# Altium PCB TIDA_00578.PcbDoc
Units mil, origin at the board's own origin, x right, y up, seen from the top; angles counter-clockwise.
Board outline 1181.1 x 1181.1 mil, 2 copper layers (Top Layer, Bottom Layer); 21 components, 9 nets, 32 pads, 7 vias.
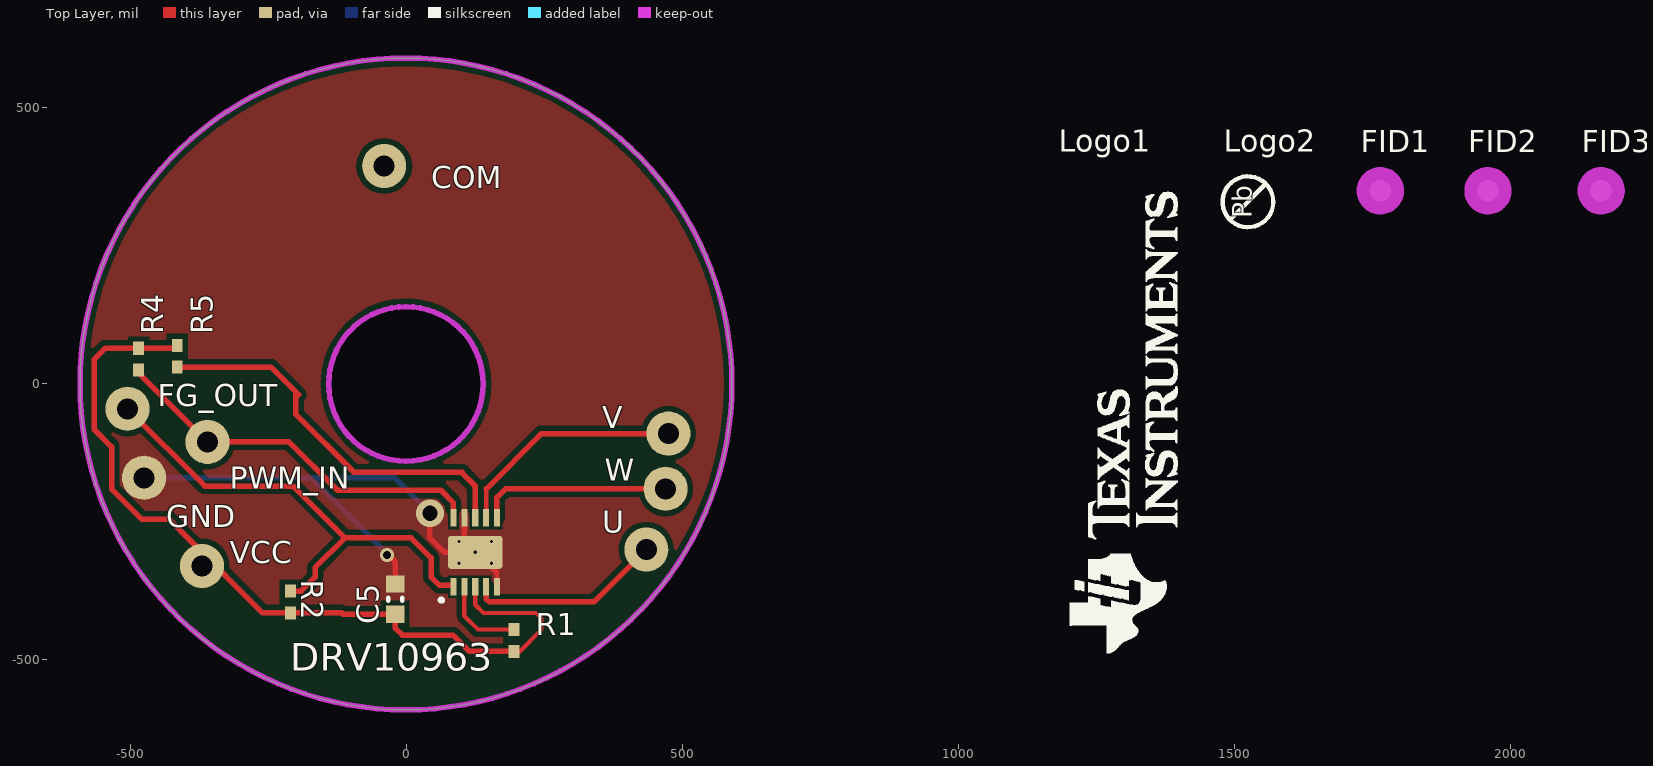
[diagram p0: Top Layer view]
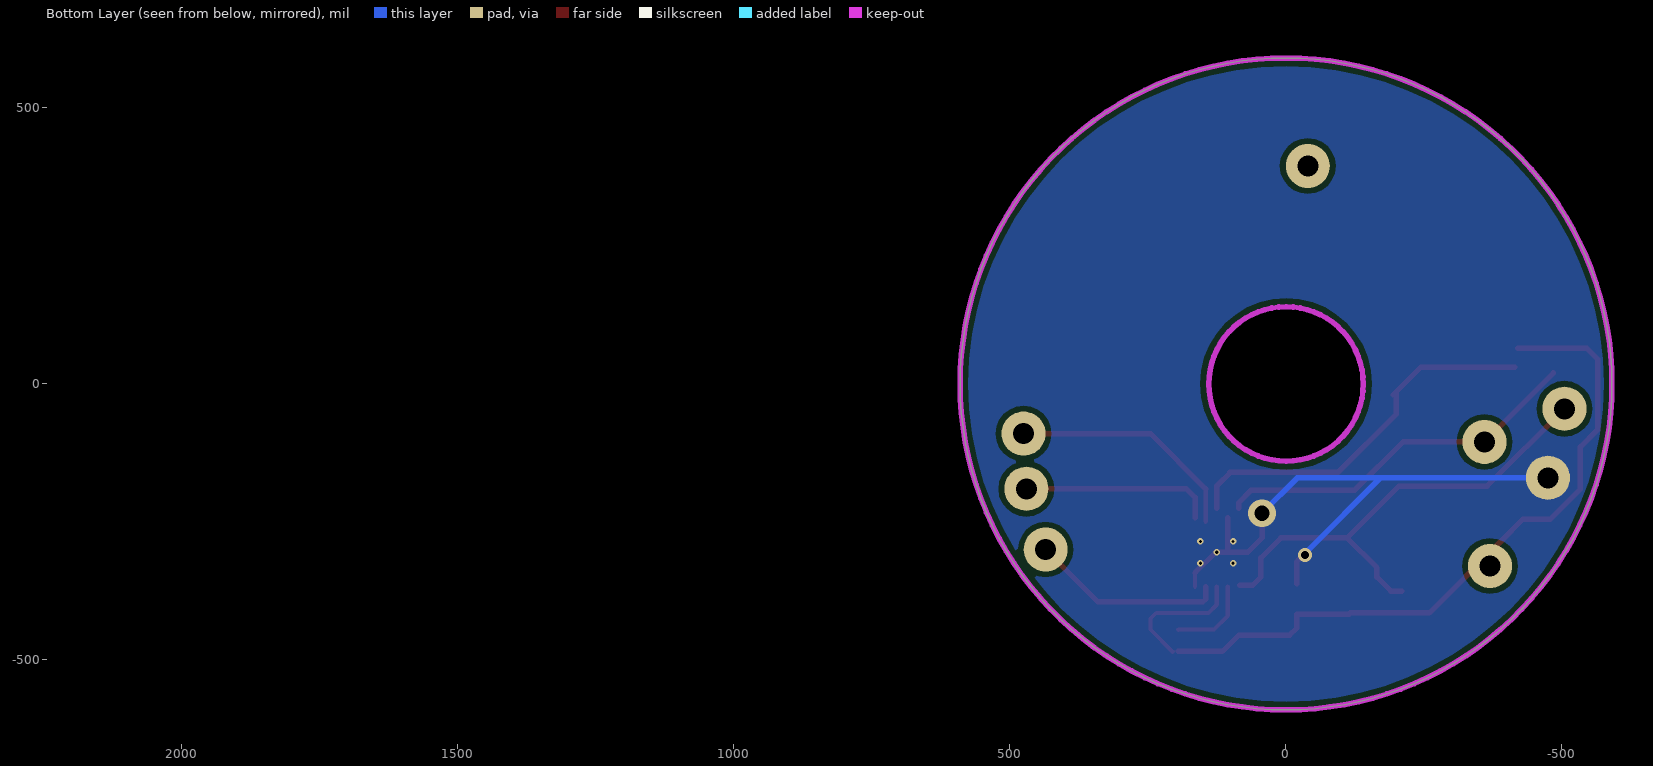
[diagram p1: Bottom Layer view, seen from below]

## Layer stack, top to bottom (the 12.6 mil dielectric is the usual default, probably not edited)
Top Solder: solder mask 0.4, Solder Resist, Dk 3.5
Top Layer: signal copper 1.4
Dielectric1: dielectric 12.6, FR-4, Dk 4.8
Bottom Layer: signal copper 1.4
Bottom Solder: solder mask 0.4, Solder Resist, Dk 3.5

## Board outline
-591.1,0 ccw(c-0.55,0) -0.55,-590.55 ccw(c-0.55,0) 590,0 ccw(c-0.55,0) -0.55,590.55 ccw(c-0.55,0)
cut-out: -140.55,0 ccw(c-0.55,0) -0.55,-140 ccw(c-0.55,0) 139.45,0 ccw(c-0.55,0) -0.55,140 ccw(c-0.55,0)

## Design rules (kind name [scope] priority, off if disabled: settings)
Clearance PAD2CLEAR [InComponent('DRV10963')] p1: gap=5
Clearance Clearance_1 [All] p2: gap=10
PolygonConnect PolygonConnect_3 [All vs IsNamedPolygon('Bottom Layer--gnd')] p1: connectstyle=Direct reliefconductorwidth=10 reliefentries=4 polygonreliefangle="90 Angle" airgapwidth=10
PolygonConnect PolygonConnect_2 [All vs IsNamedPolygon('Top Layer-No Net')] p2: connectstyle=Direct reliefconductorwidth=10 reliefentries=4 polygonreliefangle="90 Angle" airgapwidth=10
PolygonConnect PolygonConnect_1 [All vs IsNamedPolygon('Top Layer-No Net')] p3: connectstyle=Direct reliefconductorwidth=10 reliefentries=4 polygonreliefangle="90 Angle" airgapwidth=10
PolygonConnect [All] p4: connectstyle=Relief reliefconductorwidth=10 reliefentries=4 polygonreliefangle="90 Angle" airgapwidth=10
RoutingVias [All] p1: holewidth=28 width=50 viastyle="Through Hole" minholewidth=28 minwidth=50 maxholewidth=28 maxwidth=50
SilkToSolderMaskClearance SilkscreenOverComponentPads [IsPad] p1: minsilkscreentomaskgap=10 clearancetoexposedcopper=TRUE
SolderMaskExpansion [All] p1: expansion=4
UnpouredPolygon [All] p1: allowunpoured=FALSE
Width [All] p1: maxlimit=10 minlimit=6 preferedwidth=10
28 further rules are at their usual default settings.

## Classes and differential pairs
component class TID_Hardware: !PCB FID1 FID2 FID3 Logo1 Logo2 ZZ2 ZZ3 ZZ4
component class Logo: Logo1
component class FiducialMark: FID1 FID2 FID3
component class AssemblyNote: ZZ2 ZZ3 ZZ4
component class "DRV10963FAN REF": C5 DRV10963 FG_OUT GND PWM_IN R1 R2 R4 R5 U V VCC W

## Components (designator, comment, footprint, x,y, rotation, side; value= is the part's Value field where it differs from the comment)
C5 "C0603C225K8PACTU" 0603L -20,-390 r90 top
DRV10963 "DRV10963DSN" "DSN with thermal vias" 125,-305 r90 top
FG_OUT "TESTPOINT" TESTPOINT -505,-45 r90 top
FID1 "Fiducial" Fiducial10-20 1765,350 r0 top
FID2 "Fiducial" Fiducial10-20 1960,350 r0 top
FID3 "Fiducial" Fiducial10-20 2165,350 r0 top
GND "TESTPOINT" TESTPOINT -475,-170 r0 top
Logo1 "Texas Instruments" TI_Stacked_Overlay_Small 1300,-70 r90 top
Logo2 "Pb-Free Symbol" Pb-Free_Overlay_Small 1525,330 r90 top
PWM_IN "TESTPOINT" TESTPOINT -360,-105 r90 top
R1 "CRCW0402100KJNED" 0402L 195,-465 r270 top
R2 "CRCW0402100KJNED" 0402L -210,-395 r270 top
R4 "ERJ-2GE0R00X" 0402L -485,45 r270 top
R5 "CRCW040210K0JNED" 0402L -415,50 r90 top
U "TESTPOINT" TESTPOINT 435,-300 r90 top
V "TESTPOINT" TESTPOINT 475,-90 r90 top
VCC "TESTPOINT" TESTPOINT -370,-330 r0 top
W "TESTPOINT" TESTPOINT 470,-190 r90 top
ZZ2 "These assemblies are ESD sensitive, ESD precautions shall be observed." AssemblyNote -435,795 r0 top
ZZ3 "These assemblies must be clean and free from flux and all contaminants. Use of no clean flux is not acceptable." AssemblyNote -435,975 r0 top
ZZ4 "These assemblies must comply with workmanship standards IPC-A-610 Class 2, unless otherwise specified." AssemblyNote -435,1150 r0 top

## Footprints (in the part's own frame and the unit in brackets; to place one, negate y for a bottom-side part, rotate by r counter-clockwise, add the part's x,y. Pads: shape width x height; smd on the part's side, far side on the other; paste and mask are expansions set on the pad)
0402L [mm] "0402 from SM-752 data"
  rect 0.6x0.5 smd: 1(-0.5,0) 2(0.5,0)
  body extent -0.55,-0.3 0.55,0.3, height 0.6
0603L [mm] "0603 from SM-752 data"
  rect 0.8x0.85 smd: 1(-0.7,0) 2(0.7,0)
  silkscreen extent -0.07,-0.33 0.07,0.33, body extent -0.87,-0.47 0.87,0.47, height 0.85
AssemblyNote [mil] "Assembly Note"
"DSN with thermal vias" [mm] "DSN footprint"
  rect 0.825x0.28 smd mask+0.07: 1(-1.587,1.001) 2(-1.587,0.5) 3(-1.587,0) 4(-1.587,-0.5) 5(-1.587,-1.001) 6(1.587,-1.001) 7(1.587,-0.5) 8(1.587,0) 9(1.587,0.5) 10(1.587,1.001)
  rrect20% 1.52x2.52 smd mask+0.07: 11(0,0)
  silkscreen extent -2.24,1.52 -2.16,1.6
Fiducial10-20 [mm]
  round 1 smd mask+0.5: 1(0,0)
  Top Layer keep-out circle w1.178: c0,0 r0.5
Pb-Free_Overlay_Small [mil]
  silkscreen extent -46,-46 46,46
TESTPOINT [mil]
  round 80 hole 37.99: 1(0,0)
TI_Stacked_Overlay_Small [mil]
  silkscreen extent -418,-98 418,98

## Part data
C5: "CAP, CERM, 2.2uF, 10V, +/-10%, X5R, 0603"
DRV10963: library part DRV10963BDSN
FG_OUT GND PWM_IN U V VCC W: "TEST POINT.  No entry in BOM."
FID1 FID2 FID3: "Fiducial mark.  There is nothing to buy or mount."
Logo1: library part TI_Logo, "Texas Instrument Corporate Signature"
Logo2: library part Pb-Free
R1 R2: "RES, 100k ohm, 5%, 0.063W, 0402"
R4: "RES, 0 ohm, 5%, 0.063W, 0402"
R5: "RES, 10k ohm, 5%, 0.063W, 0402"
ZZ2 ZZ3 ZZ4: library part AssemblyNote

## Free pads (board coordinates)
  round 80 hole 38: 1(-40,395)

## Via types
v1: diameter 11.81, hole 5.91, Top Layer to Bottom Layer, 5 vias
v2: diameter 50, hole 28, Top Layer to Bottom Layer, 1 vias
v3: diameter 25, hole 14, Top Layer to Bottom Layer, 1 vias

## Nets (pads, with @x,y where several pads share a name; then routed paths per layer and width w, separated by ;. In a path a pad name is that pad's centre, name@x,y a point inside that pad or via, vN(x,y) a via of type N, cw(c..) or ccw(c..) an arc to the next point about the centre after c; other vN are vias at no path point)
FG_OUT: DRV10963.1 FG_OUT.1 R2.1 | length 890
  Top Layer w10: FG_OUT.1 -365,-185 -205,-185 -111.05,-278.95 ; R2.1 -190.32,-375.32 -165,-350 -165,-332.9 -111.05,-278.95 ; DRV10963.1@83.1,-365 60,-365 45,-350 45,-315 8.95,-278.95 -111.05,-278.95
FGS: DRV10963.2 R1.1 | length 152.9
  Top Layer w8: DRV10963.2 105.3,-420.3 130,-445 194.68,-445 R1.1
FWD_REV: DRV10963.8 R5.1 | length 700
  Top Layer w10: R5.1 -245.32,30.32 -200,-15 ; -195,-20 -200,-15 ; 100.5,-160.5 125,-185 125,-225 ; 101,-160 -95,-160 -200,-55 -200,-15
GND: C5.2 DRV10963.5 DRV10963.9 DRV10963.11 GND.1 | length 1070
  Top Layer w8: DRV10963.5 164.4,-342
  Top Layer w10: -24,-318 -20,-322 C5.2 ; v2(43,-234) 43,-279 69,-305 DRV10963.11@105,-305 ; DRV10963.9 105.3,-261 105,-261.3 DRV10963.11@105,-305 ; 164.4,-342 127.4,-305 v1(125,-305) DRV10963.11@105,-305
  Bottom Layer w10: GND.1@-485,-170 -172,-170 ; v3@-38.5,-303.5 -172,-170 ; v2(43,-234) -21,-170 -172,-170
  other v1: 95.47,-324.68 154.53,-324.68 95.47,-285.31 154.53,-285.31
  other v3: -35,-310
PWM_IN: DRV10963.10 PWM_IN.1 R4.2 | length 677.3
  Top Layer w10: R4.2@-485,20 PWM_IN.1 -212.5,-105 -125,-192.5 62.5,-192.5 85,-215 85,-225
U: DRV10963.4 U.1 | length 354
  Top Layer w8: 144.7,-389.7 150,-395
  Top Layer w10: 144.7,-389.7 DRV10963.4 ; 150,-395 340,-395 U.1
V: DRV10963.7 V.1 | length 431.4
  Top Layer w8: DRV10963.7@145,-250 145,-190
  Top Layer w10: 145,-190 245,-90 V.1
VCC: C5.1 DRV10963.3 R1.2 R2.2 R4.1 R5.2 VCC.1 | length 1506.1
  Top Layer w8: DRV10963.3 125,-400 140,-415 235,-415 245,-425 245,-445 205,-485
  Top Layer w10: R4.1 R5.2@-420,64.68 ; R4.1@-485,65 -545,65 -565,45 -565,-83 -534,-114 -534,-190.3 -479.3,-245 -430,-245 -390,-285 -260.31,-414.69 R2.2 -117,-414.69 -114.13,-417.56 C5.1 -20,-442 -7,-455 85,-455 114.69,-484.69 R1.2
W: DRV10963.6 W.1 | length 349
  Top Layer w10: DRV10963.6 164.4,-205.6 180,-190 W.1
pads on no net: FID1.1 FID2.1 FID3.1

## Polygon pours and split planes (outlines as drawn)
GND on Bottom Layer "Bottom Layer--gnd" (solid, remove dead copper, pour order 6): -591.1,0 ccw(c-0.55,0) -0.55,-590.55 ccw(c-0.55,0) 590,0 ccw(c-0.55,0) -0.55,590.55 ccw(c-0.55,0)
GND on Top Layer "Top Layer-No Net" (solid, remove dead copper, pour order 3): -591.1,0 ccw(c-0.55,0) -0.55,-590.55 ccw(c-0.55,0) 590,0 ccw(c-0.55,0) -0.55,590.55 ccw(c-0.55,0)

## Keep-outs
Keep-Out Layer:
  circle w10: c-0.55,0 r140
  circle w10: c-0.55,0 r590.55

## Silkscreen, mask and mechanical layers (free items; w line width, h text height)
Top Overlay:
  text "COM" at 45,355 h40
Mechanical 1:
  circle w10: c-0.55,0 r140
  circle w10: c0,0 r590.55
  lines w10: -600.04,-660 -599.96,-680 ; -540.08,-649.75 -600,-670 ; -539.92,-689.75 -600,-670 ; -355.89,-668.98 -600,-670 ; 355.89,-666.02 600,-665 ; 539.92,-645.25 600,-665 ; 540.08,-685.25 600,-665 ; 599.96,-655 600.04,-675 ; 685.49,-549.84 705,-610 ; 694.51,555.17 715,615 ; 695,-609.92 715,-610.08 ; 705,615.08 725,614.92 ; 706.85,-383.37 705,-610 ; 713.15,388.37 715,615 ; 725.49,-550.17 705,-610 ; 734.51,554.84 715,615
  text "1225.041 (mil)" at 742.92,-373.66 h60 r89.53
  text "1200.01 (mil)" at -345.74,-704.93 h60 r0.24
